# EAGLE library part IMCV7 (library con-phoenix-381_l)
Invertierter Mini-Combicon 3.81mm vertikal 7-polig IMCV 1,5/7-G-3,81 (ohne Gegenstecker)
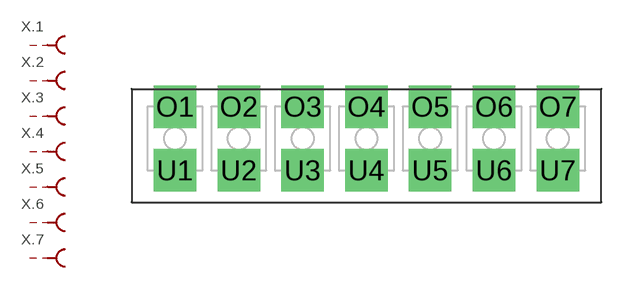
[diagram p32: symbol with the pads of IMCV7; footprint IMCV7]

Designator prefix X; gates .4=MCBU .3=MCBU .2=MCBU .1=MCBU .5=MCBU .6=MCBU .7=MCBU

## IMCV7  [IMCV7]
O1  .1:S  pas
O2  .2:S  pas
O3  .3:S  pas
O4  .4:S  pas
O5  .5:S  pas
O6  .6:S  pas
O7  .7:S  pas
U1  .1:SK  pas
U2  .2:SK  pas
U3  .3:SK  pas
U4  .4:SK  pas
U5  .5:SK  pas
U6  .6:SK  pas
U7  .7:SK  pas

## Footprint IMCV7 (pad centres in mm)
Mini-Combicon 3.81mm vertical 7-polig invertiert (ohne Gegenstecker)
drill 1.3 pad 2.54 square: O1 -11.43,1.905; O2 -7.62,1.905; O3 -3.81,1.905; O4 0,1.905; O5 3.81,1.905; O6 7.62,1.905; O7 11.43,1.905; U1 -11.43,-1.905; U2 -7.62,-1.905; U3 -3.81,-1.905; U4 0,-1.905; U5 3.81,-1.905; U6 7.62,-1.905; U7 11.43,-1.905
